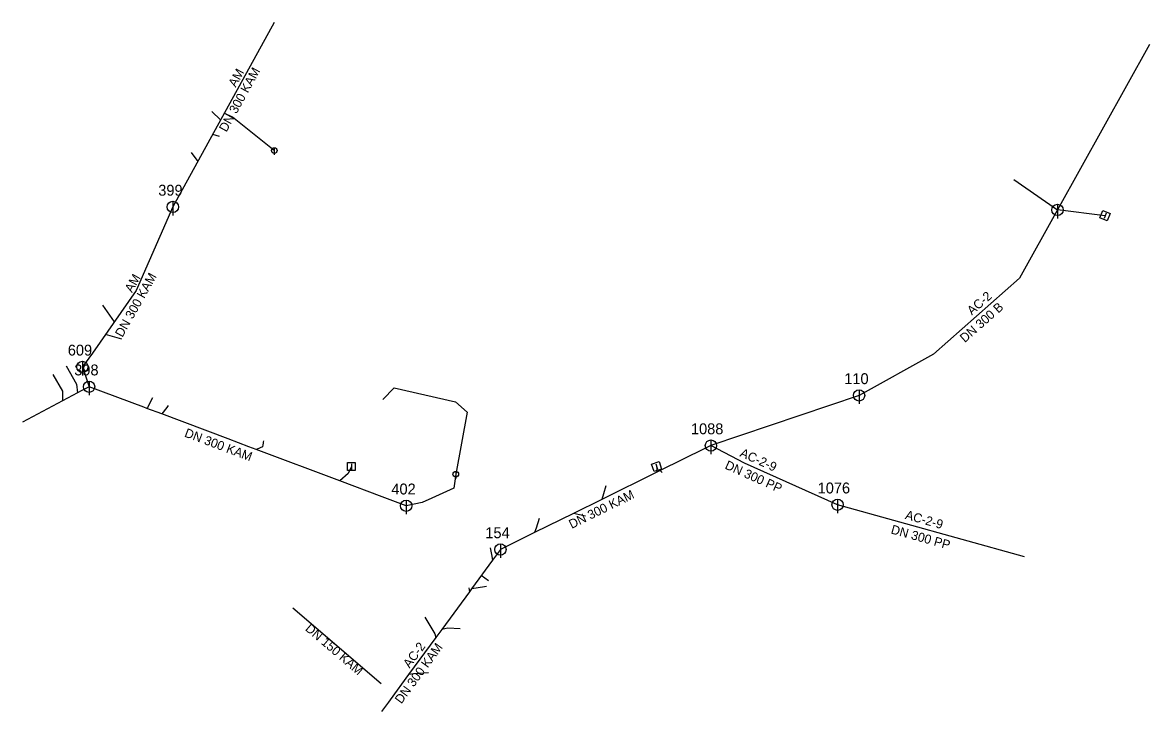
# Model space of a CAD drawing. Extents: x -508836 to -508637, y -1104379 to -1104257.
import ezdxf

# ---------------------------------------------------------------- set-up
doc = ezdxf.new("R2010")
doc.units = 0
for name, color, linetype in [('_pripojka_kanal_destova_prevzato_z_dokumentace_', 7, 'Continuous'), ('_pripojka_kanal_destova_priblizne_', 7, 'Continuous'), ('_pripojka_kanal_jednotna_prevzato_z_dokumentace_', 7, 'Continuous'), ('_pripojka_kanal_jednotna_priblizne_', 7, 'Continuous'), ('_pripojka_kanal_splaskova_priblizne_', 7, 'Continuous'), ('_stoka_jednotna_smvak_prevzato_z_dokumentace_', 7, 'Continuous'), ('_stoka_jednotna_smvak_priblizne_', 7, 'Continuous'), ('_stoka_splaskova_provozovana_prevzato_z_dokumentace_', 7, 'Continuous'), ('Default', 7, 'Continuous'), ('MoLevel 1', 7, 'Continuous'), ('MoLevel 119', 7, 'Continuous'), ('MoLevel 120', 7, 'Continuous'), ('MoLevel 124', 7, 'Continuous'), ('MoLevel 2', 7, 'Continuous'), ('MoLevel 57', 7, 'Continuous'), ('MoLevel 63', 7, 'Continuous'), ('MoLevel 68', 7, 'Continuous'), ('MoLevel 69', 7, 'Continuous'), ('MoLevel 84', 7, 'Continuous'), ('MoLevel 85', 7, 'Continuous')]:
    doc.layers.add(name, color=color, linetype=linetype)

# ---------------------------------------------------------------- blocks, each defined once
blk = doc.blocks.new('_vpust_')
at = {"layer": 'Default'}
blk.add_line((0, 0.000025), (0, -0.000025), dxfattribs=at)
blk.add_lwpolyline([(-0.000035, 0.000035), (0.000035, 0.000035), (0.000035, -0.000035), (-0.000035, -0.000035), (-0.000035, 0.000035)], dxfattribs=at)
blk = doc.blocks.new('_sachta_kanal_prip_')
at = {"layer": 'Default'}
blk.add_line((0, 0.00005), (0, -0.000075), dxfattribs=at)
blk.add_circle((0, 0), 0.00005, dxfattribs=at)
blk = doc.blocks.new('_sachta_kanal_prevzato_z_dokumentace_')
at = {"layer": 'Default'}
blk.add_line((0, 0.00005), (0, -0.000075), dxfattribs=at)
blk.add_circle((0, 0), 0.00005, dxfattribs=at)

msp = doc.modelspace()

# ---------------------------------------------------------------- linework, layer by layer
at = {"layer": '_pripojka_kanal_destova_prevzato_z_dokumentace_'}
msp.add_line((-508723.85, -1104335.96), (-508723.82, -1104336.61), dxfattribs=at)
msp.add_lwpolyline([(-508777.86, -1104335.61), (-508778.43, -1104336.86), (-508779.91, -1104338.14)], dxfattribs=at)
at = {"layer": '_pripojka_kanal_destova_priblizne_'}
for p, q in [((-508644.55, -1104291.24), (-508652.98, -1104290.21)), ((-508723.87, -1104335.61), (-508723.85, -1104335.96))]:
    msp.add_line(p, q, dxfattribs=at)
at = {"layer": '_pripojka_kanal_jednotna_prevzato_z_dokumentace_'}
for p, q in [((-508826.48, -1104321.05), (-508826.29, -1104322.56)), ((-508828.93, -1104322.25), (-508828.92, -1104323.97)), ((-508813.89, -1104325.16), (-508814.02, -1104325.32)), ((-508810.52, -1104325.15), (-508811.41, -1104326.3)), ((-508793.42, -1104331.07), (-508793.45, -1104331.3)), ((-508722.91, -1104336.68), (-508723.26, -1104336.33)), ((-508733.24, -1104340.44), (-508733.54, -1104341.41)), ((-508738.03, -1104344.04), (-508738.6, -1104343.91)), ((-508745.18, -1104346.49), (-508745.45, -1104347.3)), ((-508753.07, -1104351.19), (-508752.89, -1104352.18)), ((-508757.09, -1104357.06), (-508756.98, -1104357.76)), ((-508755.79, -1104357.11), (-508756.61, -1104357.25)), ((-508763.07, -1104365.22), (-508762.91, -1104365.83)), ((-508760.78, -1104364.21), (-508761.86, -1104364.41)), ((-508766.73, -1104372.27), (-508767.73, -1104372.41))]:
    msp.add_line(p, q, dxfattribs=at)
for points in [[(-508793.45, -1104331.3), (-508793.47, -1104331.44), (-508793.52, -1104331.77), (-508793.56, -1104332.09), (-508794.52, -1104332.52), (-508794.68, -1104332.59)], [(-508763.64, -1104341.2), (-508765.33, -1104341.98), (-508768.17, -1104342.54)]]:
    msp.add_lwpolyline(points, dxfattribs=at)
at = {"layer": '_pripojka_kanal_jednotna_priblizne_'}
for p, q in [((-508802.56, -1104272.8), (-508800.98, -1104274.27)), ((-508801.21, -1104277.22), (-508802.39, -1104276.84)), ((-508806.21, -1104280.03), (-508805.01, -1104281.62)), ((-508660.72, -1104284.84), (-508652.98, -1104290.21)), ((-508821.87, -1104307.07), (-508819.8, -1104310.01)), ((-508818.47, -1104313.08), (-508821.37, -1104312.25)), ((-508830.67, -1104319.3), (-508828.93, -1104322.25)), ((-508828.31, -1104317.81), (-508826.48, -1104321.05)), ((-508813.06, -1104323.46), (-508813.89, -1104325.16)), ((-508810.27, -1104324.79), (-508810.52, -1104325.15)), ((-508732.83, -1104339), (-508733.24, -1104340.44)), ((-508744.67, -1104344.81), (-508745.18, -1104346.49)), ((-508736.48, -1104344.39), (-508738.03, -1104344.04)), ((-508753.33, -1104349.98), (-508753.07, -1104351.19)), ((-508753.59, -1104355.81), (-508754.88, -1104354.9)), ((-508753.99, -1104356.8), (-508755.79, -1104357.11)), ((-508788.21, -1104360.59), (-508772.6, -1104373.97)), ((-508764.88, -1104362.27), (-508763.07, -1104365.22)), ((-508758.6, -1104364.3), (-508760.78, -1104364.21)), ((-508764.23, -1104372.07), (-508766.73, -1104372.27))]:
    msp.add_line(p, q, dxfattribs=at)
msp.add_lwpolyline([(-508791.49, -1104279.69), (-508798.88, -1104273.79), (-508800.34, -1104273.1)], dxfattribs=at)
at = {"layer": '_pripojka_kanal_splaskova_priblizne_'}
for points in [[(-508772.31, -1104323.73), (-508770.28, -1104321.67), (-508759.46, -1104324.13), (-508757.39, -1104326), (-508759.39, -1104336.96)], [(-508759.39, -1104336.96), (-508759.72, -1104339.42), (-508763.64, -1104341.2)]]:
    msp.add_lwpolyline(points, dxfattribs=at)
at = {"layer": '_stoka_jednotna_smvak_prevzato_z_dokumentace_'}
for p, q in [((-508791.52, -1104257.05), (-508809.44, -1104289.68)), ((-508636.71, -1104260.93), (-508652.98, -1104290.21)), ((-508823.67, -1104315.55), (-508825.44, -1104317.97)), ((-508688.07, -1104323.02), (-508714.27, -1104331.89)), ((-508714.27, -1104331.89), (-508715.34, -1104332.42))]:
    msp.add_line(p, q, dxfattribs=at)
for points in [[(-508652.98, -1104290.21), (-508659.7, -1104302.3), (-508674.9, -1104315.7), (-508688.07, -1104323.02)], [(-508825.44, -1104317.97), (-508824.73, -1104320.09), (-508824.26, -1104321.48)], [(-508824.26, -1104321.48), (-508825.77, -1104322.28), (-508826.19, -1104322.5), (-508826.29, -1104322.56), (-508828.92, -1104323.97), (-508836.02, -1104327.77)], [(-508768.17, -1104342.54), (-508772.44, -1104340.94), (-508779.91, -1104338.14), (-508794.68, -1104332.59), (-508795.97, -1104332.1), (-508799.64, -1104330.72), (-508811.41, -1104326.3), (-508814.02, -1104325.32), (-508814.59, -1104325.11), (-508824.26, -1104321.48)], [(-508715.34, -1104332.42), (-508723.26, -1104336.33), (-508723.82, -1104336.61), (-508733.54, -1104341.41), (-508738.6, -1104343.91), (-508745.45, -1104347.3), (-508751.5, -1104350.28)], [(-508751.5, -1104350.28), (-508752.89, -1104352.18), (-508756.61, -1104357.25), (-508756.98, -1104357.76), (-508761.86, -1104364.41), (-508762.91, -1104365.83), (-508767.73, -1104372.41), (-508771.02, -1104376.89), (-508771.29, -1104377.26), (-508772.52, -1104378.93)]]:
    msp.add_lwpolyline(points, dxfattribs=at)
at = {"layer": '_stoka_jednotna_smvak_priblizne_'}
msp.add_lwpolyline([(-508809.44, -1104289.68), (-508815.94, -1104304.47), (-508823.67, -1104315.55)], dxfattribs=at)
at = {"layer": '_stoka_splaskova_provozovana_prevzato_z_dokumentace_'}
msp.add_line((-508658.84, -1104351.55), (-508691.86, -1104342.36), dxfattribs=at)
msp.add_lwpolyline([(-508691.86, -1104342.36), (-508708.31, -1104334.99), (-508714.27, -1104331.89)], dxfattribs=at)

# ---------------------------------------------------------------- block references
at = {"layer": 'MoLevel 119', "xscale": 20000, "yscale": 20000}
for p in [(-508809.44, -1104289.68), (-508652.98, -1104290.21), (-508825.44, -1104317.97), (-508824.26, -1104321.48), (-508688.07, -1104323.02), (-508714.27, -1104331.89), (-508691.86, -1104342.36), (-508768.17, -1104342.54), (-508751.5, -1104350.28)]:
    msp.add_blockref('_sachta_kanal_prevzato_z_dokumentace_', p, dxfattribs=at)
at = {"layer": 'MoLevel 57', "xscale": 10000, "yscale": 10000}
for p in [(-508791.49, -1104279.69), (-508759.39, -1104336.96)]:
    msp.add_blockref('_sachta_kanal_prip_', p, dxfattribs=at)
at = {"layer": 'MoLevel 63', "xscale": 20000}
for p, yscale, rotation in [((-508644.55, -1104291.24), 20000, -22.12633480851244), ((-508723.87, -1104335.61), 19999.999999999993, 18.4662173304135)]:
    msp.add_blockref('_vpust_', p, dxfattribs=dict(at, yscale=yscale, rotation=rotation))
at = {"layer": 'MoLevel 63', "xscale": 20000, "yscale": 20000}
msp.add_blockref('_vpust_', (-508777.86, -1104335.61), dxfattribs=at)

# ---------------------------------------------------------------- texts
at = {"layer": 'MoLevel 1'}
msp.add_text('DN 300 KAM', height=1.605, rotation=60.686, dxfattribs=at).set_placement((-508818.36, -1104312.85))
at = {"layer": 'MoLevel 120'}
for s, p in [('399', (-508812.01, -1104287.68)), ('609', (-508828.01, -1104315.97)), ('398', (-508826.87, -1104319.48)), ('110', (-508690.68, -1104321.02)), ('1088', (-508717.8, -1104329.89)), ('402', (-508770.78, -1104340.54)), ('1076', (-508695.39, -1104340.36)), ('154', (-508754.16, -1104348.28))]:
    msp.add_text(s, height=1.926, dxfattribs=at).set_placement(p)
at = {"layer": 'MoLevel 124'}
msp.add_text('DN 150 KAM', height=1.605, rotation=319.4092, dxfattribs=at).set_placement((-508786.14, -1104364.48))
at = {"layer": 'MoLevel 2'}
msp.add_text('AM', height=1.605, rotation=60.686, dxfattribs=at).set_placement((-508816.65, -1104304.94))
at = {"layer": 'MoLevel 68'}
for s, rotation, p in [('DN 300 KAM', 61.2295, (-508799.96, -1104276.54)), ('DN 300 B', 41.3987, (-508669.37, -1104313.76)), ('DN 300 KAM', 339.405, (-508807.5, -1104330.28)), ('DN 300 KAM', 26.2814, (-508738.9, -1104346.65)), ('DN 300 KAM', 53.7764, (-508769.02, -1104377.69))]:
    msp.add_text(s, height=1.605, rotation=rotation, dxfattribs=at).set_placement(p)
at = {"layer": 'MoLevel 69'}
for s, rotation, p in [('AM', 61.2295, (-508798.31, -1104268.61)), ('AC-2', 41.3987, (-508668.11, -1104308.91)), ('AC-2', 53.7764, (-508767.56, -1104371.38))]:
    msp.add_text(s, height=1.605, rotation=rotation, dxfattribs=at).set_placement(p)
at = {"layer": 'MoLevel 84'}
for rotation, p in [(335.8665, (-508711.93, -1104335.92)), (344.4473, (-508682.55, -1104347.42))]:
    msp.add_text('DN 300 PP', height=1.605, rotation=rotation, dxfattribs=at).set_placement(p)
at = {"layer": 'MoLevel 85'}
for rotation, p in [(335.8665, (-508709.29, -1104333.75)), (344.4473, (-508680.03, -1104344.85))]:
    msp.add_text('AC-2-9', height=1.605, rotation=rotation, dxfattribs=at).set_placement(p)

doc.saveas('drawing.dxf')
